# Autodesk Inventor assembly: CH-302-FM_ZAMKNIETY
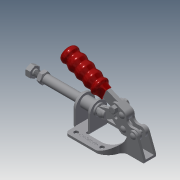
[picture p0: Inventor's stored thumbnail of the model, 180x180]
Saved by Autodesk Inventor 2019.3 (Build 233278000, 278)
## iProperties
Company: Î¢ÈíÖÐ¹ú
Created: 2013-03
Part Number: CH-302-FM_ZAMKNIETY
Material: Ogólny
Description: STEP AP203
Document SubType Name: Assembly
Designer: CADENGINEERING4
Sending System: SolidWorks 2010
Preprocessor: SwSTEP 2.0
Title: CH-302-FM.STEP
Author: Î¢ÈíÓÃ»§
Revision Number: ÈÎºÎ
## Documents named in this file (14)
- D:\Vault_2016\Projekty\STRONA\Push-pull clamp\CH-302-FM\CH-302-FM_ZAMKNIETY.iam
- D:\Vault_2016\Projekty\STRONA\Push-pull clamp\CH-302-FM\CH-302-FM-03 HANDLE.ipt
- D:\Vault_2016\Projekty\STRONA\Push-pull clamp\CH-302-FM\CH-302-FM-04 CONNECTING-PLATE.ipt
- D:\Vault_2016\Projekty\STRONA\Push-pull clamp\CH-302-FM\CH-302-FM-02 CREST STALK.ipt
- D:\Vault_2016\Projekty\STRONA\Push-pull clamp\CH-302-FM\CH-302-FM-09.ipt
- D:\Vault_2016\Projekty\STRONA\Push-pull clamp\CH-302-FM\M8 Nut.ipt
- D:\Vault_2016\Projekty\STRONA\Push-pull clamp\CH-302-FM\CH-302-FM-06.ipt
- D:\Vault_2016\Projekty\STRONA\Push-pull clamp\CH-302-FM\CH-302-FM-08.ipt
- D:\Vault_2016\Projekty\STRONA\Push-pull clamp\CH-302-FM\M5 Nut.ipt
- D:\Vault_2016\Projekty\STRONA\Push-pull clamp\CH-302-FM\CH-302-FM-01 BASE.ipt
- D:\Vault_2016\Projekty\STRONA\Push-pull clamp\CH-302-FM\CH-SA-052008 SPINDLE SUPPLIED.ipt
- D:\Vault_2016\Projekty\STRONA\Push-pull clamp\CH-302-FM\CH-302-FM-05 LEAD SET.ipt
- D:\Vault_2016\Projekty\STRONA\Push-pull clamp\CH-302-FM\CH-SA-085012 SPINDLE SUPPLIED.ipt
- D:\Vault_2016\Projekty\STRONA\Push-pull clamp\CH-302-FM\CH-302-F-07.ipt
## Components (17 placed, 17 different names)
1. CH-302-FM-03 HANDLE_1
2. CH-302-FM-04 CONNECTING-PLATE_2
3. CH-302-FM-02 CREST STALK_3
4. CH-302-FM-09_4
5. M8 Nut_5
6. CH-302-FM-06_6
7. CH-302-FM-08_7
8. CH-302-FM-08_8
9. M5 Nut_9
10. CH-302-FM-01 BASE_10
11. CH-SA-052008 SPINDLE SUPPLIED_11
12. CH-302-FM-05 LEAD SET_12
13. CH-302-FM-04 CONNECTING-PLATE_13
14. CH-302-FM-08_14
15. CH-SA-085012 SPINDLE SUPPLIED_15
16. CH-302-F-07_16
17. CH-302-FM-06_17
